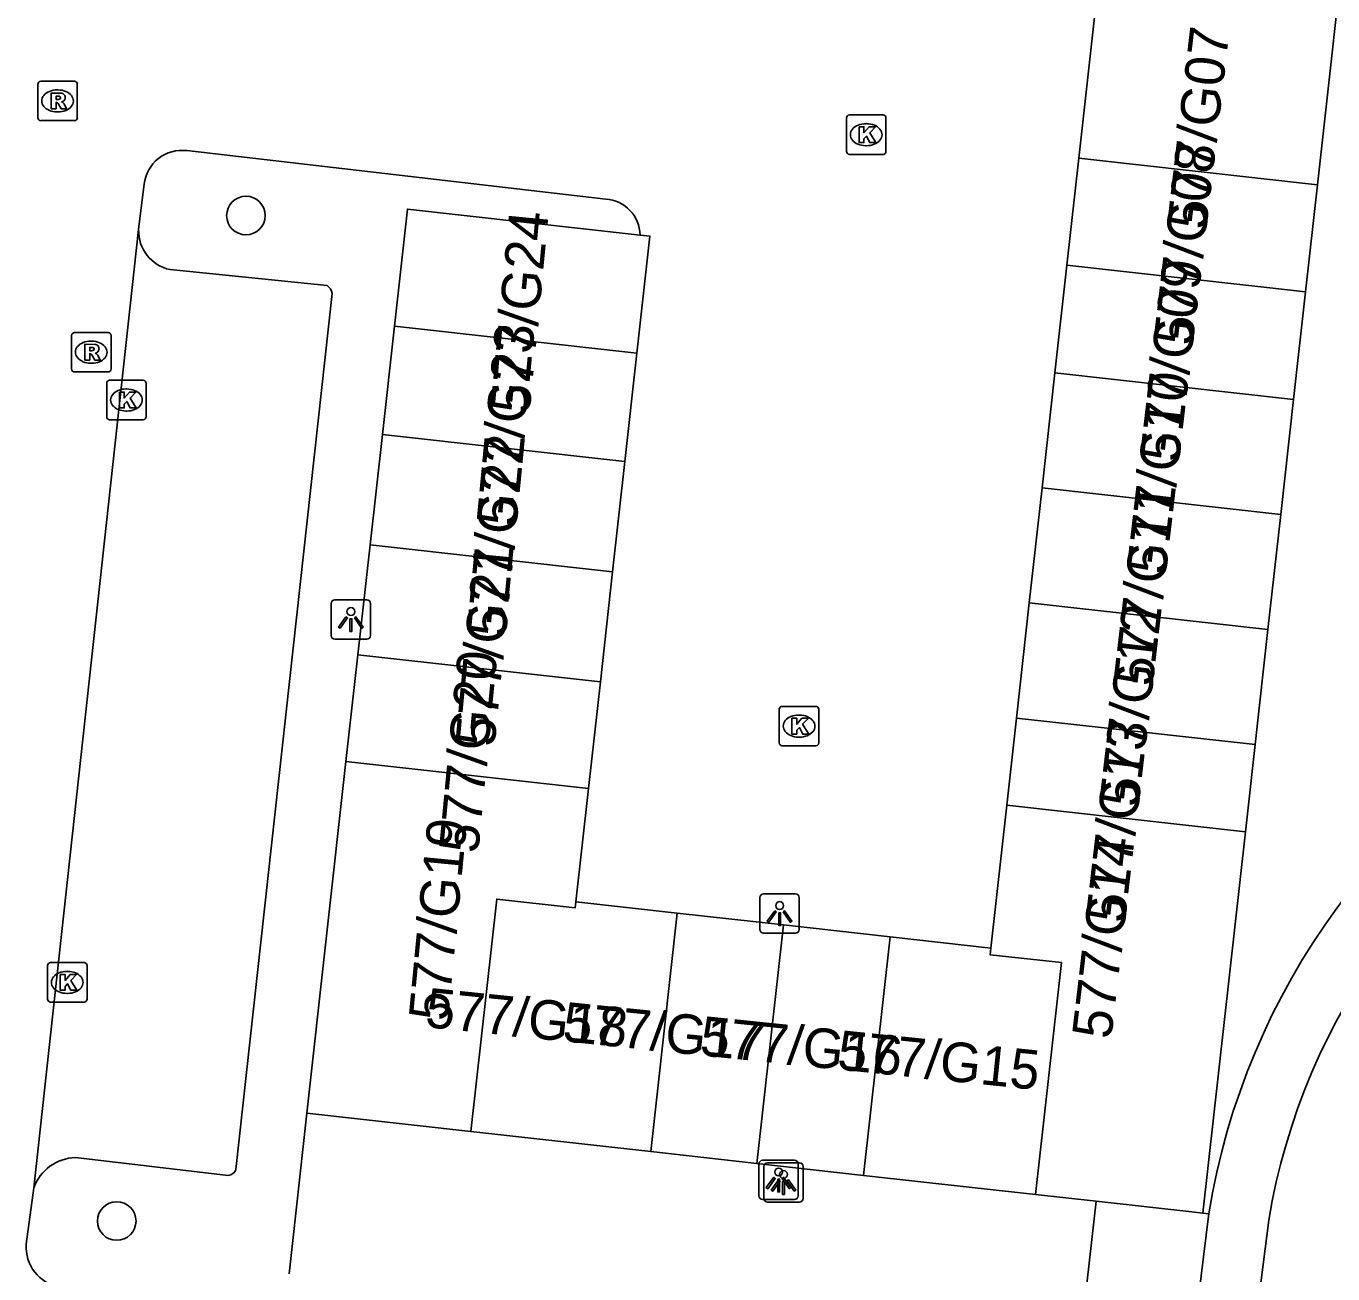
# Model space of a CAD drawing. Extents: x 162026 to 163499, y 387297 to 388169.
# Drawn here: x 162162.16 to 162195.29, y 387957.96 to 387989.59 of the extents above; entities that cross this region are included whole.
import ezdxf

# ---------------------------------------------------------------- set-up
doc = ezdxf.new("R2010")
doc.units = 0
for name, color, linetype in [('IMGEO_Boom', 7, 'Continuous'), ('IMGEO_Groenvoorziening', 7, 'Continuous'), ('IMGEO_Kolk', 7, 'Continuous'), ('IMGEO_Lichtpunt', 7, 'Continuous'), ('IMGEO_Pand', 7, 'Continuous'), ('IMGEO_Pand_nummerreeks', 7, 'Continuous'), ('IMGEO_Parkeervlak_open', 7, 'Continuous'), ('IMGEO_Rijbaan_lokaal_open', 7, 'Continuous'), ('IMGEO_Rioolput', 7, 'Continuous'), ('IMGEO_Voetpad_open', 7, 'Continuous')]:
    doc.layers.add(name, color=color, linetype=linetype)

msp = doc.modelspace()

# ---------------------------------------------------------------- linework, layer by layer
at = {"layer": 'IMGEO_Boom'}
for centre in [(162167.731, 387984.79), (162164.456, 387959.299)]:
    msp.add_circle(centre, 0.489, dxfattribs=at)
at = {"layer": 'IMGEO_Groenvoorziening'}
msp.add_lwpolyline([(162191.994, 387959.499), (162192.14, 387959.482)], dxfattribs=at)
at = {"layer": 'IMGEO_Kolk'}
for p, q in [((162182.955, 387986.414), (162182.955, 387987.266)), ((162183.03, 387987.34), (162183.882, 387987.34)), ((162183.443, 387987.12), (162183.468, 387987.12)), ((162183.956, 387987.266), (162183.956, 387986.414)), ((162183.466, 387986.56), (162183.441, 387986.56)), ((162183.882, 387986.34), (162183.03, 387986.34)), ((162164.201, 387979.688), (162164.201, 387980.54)), ((162164.276, 387980.614), (162165.128, 387980.614)), ((162165.202, 387980.54), (162165.202, 387979.688)), ((162164.689, 387980.394), (162164.714, 387980.394)), ((162164.712, 387979.834), (162164.687, 387979.834)), ((162165.128, 387979.614), (162164.276, 387979.614)), ((162181.253, 387971.42), (162181.253, 387972.272)), ((162181.328, 387972.346), (162182.18, 387972.346)), ((162182.254, 387972.272), (162182.254, 387971.42)), ((162181.741, 387972.126), (162181.766, 387972.126)), ((162181.764, 387971.566), (162181.739, 387971.566)), ((162182.18, 387971.346), (162181.328, 387971.346)), ((162162.701, 387964.923), (162162.701, 387965.775)), ((162162.776, 387965.849), (162163.628, 387965.849)), ((162163.189, 387965.629), (162163.214, 387965.629)), ((162163.702, 387965.775), (162163.702, 387964.923)), ((162163.212, 387965.069), (162163.187, 387965.069)), ((162163.628, 387964.849), (162162.776, 387964.849))]:
    msp.add_line(p, q, dxfattribs=at)
for points in [[(162182.955, 387986.414), (162182.955, 387987.266)], [(162183.03, 387987.34), (162183.882, 387987.34)], [(162183.956, 387987.266), (162183.956, 387986.414)], [(162183.276, 387987.04), (162183.399, 387987.04), (162183.399, 387986.889), (162183.529, 387987.04), (162183.693, 387987.04), (162183.547, 387986.889), (162183.7, 387986.64), (162183.548, 387986.64), (162183.463, 387986.804), (162183.399, 387986.737), (162183.399, 387986.64), (162183.276, 387986.64), (162183.276, 387987.04)], [(162183.882, 387986.34), (162183.03, 387986.34)], [(162164.201, 387979.688), (162164.201, 387980.54)], [(162164.276, 387980.614), (162165.128, 387980.614)], [(162165.202, 387980.54), (162165.202, 387979.688)], [(162164.522, 387980.314), (162164.645, 387980.314), (162164.645, 387980.163), (162164.775, 387980.314), (162164.939, 387980.314), (162164.793, 387980.163), (162164.946, 387979.914), (162164.794, 387979.914), (162164.709, 387980.078), (162164.645, 387980.011), (162164.645, 387979.914), (162164.522, 387979.914), (162164.522, 387980.314)], [(162165.128, 387979.614), (162164.276, 387979.614)], [(162181.253, 387971.42), (162181.253, 387972.272)], [(162181.328, 387972.346), (162182.18, 387972.346)], [(162182.254, 387972.272), (162182.254, 387971.42)], [(162181.574, 387972.046), (162181.697, 387972.046), (162181.697, 387971.895), (162181.827, 387972.046), (162181.991, 387972.046), (162181.845, 387971.895), (162181.998, 387971.646), (162181.846, 387971.646), (162181.761, 387971.81), (162181.697, 387971.743), (162181.697, 387971.646), (162181.574, 387971.646), (162181.574, 387972.046)], [(162182.18, 387971.346), (162181.328, 387971.346)], [(162162.701, 387964.923), (162162.701, 387965.775)], [(162162.776, 387965.849), (162163.628, 387965.849)], [(162163.702, 387965.775), (162163.702, 387964.923)], [(162163.022, 387965.549), (162163.145, 387965.549), (162163.145, 387965.398), (162163.275, 387965.549), (162163.439, 387965.549), (162163.293, 387965.398), (162163.446, 387965.149), (162163.294, 387965.149), (162163.209, 387965.313), (162163.145, 387965.246), (162163.145, 387965.149), (162163.022, 387965.149), (162163.022, 387965.549)], [(162163.628, 387964.849), (162162.776, 387964.849)]]:
    msp.add_lwpolyline(points, dxfattribs=at)
for centre, start, end in [((162183.032, 387987.264), 91.552, 178.448), ((162183.032, 387987.264), 91.552, 178.448), ((162183.88, 387987.264), 1.552, 88.448), ((162183.88, 387987.264), 1.552, 88.448), ((162183.032, 387986.416), 181.552, 268.448), ((162183.032, 387986.416), 181.552, 268.448), ((162183.88, 387986.416), 271.552, 358.448), ((162183.88, 387986.416), 271.552, 358.448), ((162164.278, 387980.538), 91.552, 178.448), ((162164.278, 387980.538), 91.552, 178.448), ((162165.126, 387980.538), 1.552, 88.448), ((162165.126, 387980.538), 1.552, 88.448), ((162164.278, 387979.69), 181.552, 268.448), ((162164.278, 387979.69), 181.552, 268.448), ((162165.126, 387979.69), 271.552, 358.448), ((162165.126, 387979.69), 271.552, 358.448), ((162181.33, 387972.27), 91.552, 178.448), ((162181.33, 387972.27), 91.552, 178.448), ((162182.178, 387972.27), 1.552, 88.448), ((162182.178, 387972.27), 1.552, 88.448), ((162181.33, 387971.422), 181.552, 268.448), ((162181.33, 387971.422), 181.552, 268.448), ((162182.178, 387971.422), 271.552, 358.448), ((162182.178, 387971.422), 271.552, 358.448), ((162162.778, 387965.773), 91.552, 178.448), ((162162.778, 387965.773), 91.552, 178.448), ((162163.626, 387965.773), 1.552, 88.448), ((162163.626, 387965.773), 1.552, 88.448), ((162162.778, 387964.925), 181.552, 268.448), ((162162.778, 387964.925), 181.552, 268.448), ((162163.626, 387964.925), 271.552, 358.448), ((162163.626, 387964.925), 271.552, 358.448)]:
    msp.add_arc(centre, 0.0765, start, end, dxfattribs=at)
for centre, major_axis, ratio, start_param, end_param in [((162183.442, 387986.84), (-0.387, 0.002), 0.722429, 4.712389, 7.853982), ((162183.467, 387986.84), (-0.39, 0.002), 0.717154, 1.570796, 4.712389), ((162164.688, 387980.114), (-0.387, 0.002), 0.722429, 4.712389, 7.853982), ((162164.713, 387980.114), (-0.39, 0.002), 0.717154, 1.570796, 4.712389), ((162181.74, 387971.846), (-0.387, 0.002), 0.722429, 4.712389, 7.853982), ((162181.765, 387971.846), (-0.39, 0.002), 0.717154, 1.570796, 4.712389), ((162163.188, 387965.349), (-0.387, 0.002), 0.722429, 4.712389, 7.853982), ((162163.213, 387965.349), (-0.39, 0.002), 0.717154, 1.570796, 4.712389)]:
    msp.add_ellipse(centre, major_axis=major_axis, ratio=ratio, start_param=start_param, end_param=end_param, dxfattribs=at)
at = {"layer": 'IMGEO_Lichtpunt'}
for p, q in [((162169.893, 387974.952), (162169.893, 387974.145)), ((162169.893, 387974.952), (162169.893, 387974.145)), ((162170.795, 387975.047), (162169.987, 387975.047)), ((162170.795, 387975.047), (162169.987, 387975.047)), ((162170.889, 387974.145), (162170.889, 387974.952)), ((162170.889, 387974.145), (162170.889, 387974.952)), ((162169.987, 387974.051), (162170.795, 387974.051)), ((162169.987, 387974.051), (162170.795, 387974.051)), ((162181.664, 387967.593), (162180.856, 387967.593)), ((162181.664, 387967.593), (162180.856, 387967.593)), ((162180.762, 387967.498), (162180.762, 387966.691)), ((162180.762, 387967.498), (162180.762, 387966.691)), ((162181.758, 387966.691), (162181.758, 387967.498)), ((162181.758, 387966.691), (162181.758, 387967.498)), ((162180.856, 387966.597), (162181.664, 387966.597)), ((162180.856, 387966.597), (162181.664, 387966.597)), ((162180.737, 387960.744), (162180.737, 387959.937)), ((162180.737, 387960.744), (162180.737, 387959.937)), ((162181.639, 387960.839), (162180.831, 387960.839)), ((162181.639, 387960.839), (162180.831, 387960.839)), ((162180.86, 387960.681), (162180.86, 387959.874)), ((162180.86, 387960.681), (162180.86, 387959.874)), ((162181.762, 387960.776), (162180.954, 387960.776)), ((162181.762, 387960.776), (162180.954, 387960.776)), ((162181.733, 387959.937), (162181.733, 387960.744)), ((162181.733, 387959.937), (162181.733, 387960.744)), ((162181.856, 387959.874), (162181.856, 387960.681)), ((162181.856, 387959.874), (162181.856, 387960.681)), ((162180.831, 387959.843), (162181.639, 387959.843)), ((162180.831, 387959.843), (162181.639, 387959.843)), ((162180.954, 387959.78), (162181.762, 387959.78)), ((162180.954, 387959.78), (162181.762, 387959.78))]:
    msp.add_line(p, q, dxfattribs=at)
for points in [[(162170.267, 387974.616), (162170.306, 387974.588), (162170.118, 387974.326), (162170.08, 387974.353), (162170.267, 387974.616)], [(162170.369, 387974.568), (162170.416, 387974.568), (162170.416, 387974.246), (162170.369, 387974.246), (162170.369, 387974.568)], [(162170.479, 387974.588), (162170.517, 387974.615), (162170.704, 387974.353), (162170.665, 387974.325), (162170.479, 387974.588)], [(162181.136, 387967.162), (162181.175, 387967.134), (162180.987, 387966.872), (162180.949, 387966.899), (162181.136, 387967.162)], [(162181.238, 387967.114), (162181.285, 387967.114), (162181.285, 387966.792), (162181.238, 387966.792), (162181.238, 387967.114)], [(162181.348, 387967.134), (162181.386, 387967.161), (162181.573, 387966.899), (162181.534, 387966.871), (162181.348, 387967.134)], [(162181.111, 387960.408), (162181.15, 387960.38), (162180.962, 387960.118), (162180.924, 387960.145), (162181.111, 387960.408)], [(162181.234, 387960.345), (162181.273, 387960.317), (162181.085, 387960.055), (162181.047, 387960.082), (162181.234, 387960.345)], [(162181.213, 387960.36), (162181.26, 387960.36), (162181.26, 387960.038), (162181.213, 387960.038), (162181.213, 387960.36)], [(162181.323, 387960.38), (162181.361, 387960.407), (162181.548, 387960.145), (162181.509, 387960.117), (162181.323, 387960.38)], [(162181.336, 387960.297), (162181.383, 387960.297), (162181.383, 387959.975), (162181.336, 387959.975), (162181.336, 387960.297)], [(162181.446, 387960.317), (162181.484, 387960.344), (162181.671, 387960.082), (162181.632, 387960.054), (162181.446, 387960.317)]]:
    msp.add_lwpolyline(points, dxfattribs=at)
for centre in [(162170.392, 387974.75), (162181.261, 387967.296), (162181.236, 387960.542), (162181.359, 387960.479)]:
    msp.add_circle(centre, 0.0994, dxfattribs=at)
for centre, start, end in [((162169.987, 387974.952), 90, 180), ((162169.987, 387974.952), 90, 180), ((162170.795, 387974.952), 0, 90), ((162170.795, 387974.952), 0, 90), ((162169.987, 387974.145), 180, 270), ((162169.987, 387974.145), 180, 270), ((162170.795, 387974.145), 270, 0), ((162170.795, 387974.145), 270, 360), ((162180.856, 387967.498), 90, 180), ((162180.856, 387967.498), 90, 180), ((162181.664, 387967.498), 0, 90), ((162181.664, 387967.498), 0, 90), ((162180.856, 387966.691), 180, 270), ((162180.856, 387966.691), 180, 270), ((162181.664, 387966.691), 270, 0), ((162181.664, 387966.691), 270, 360), ((162180.831, 387960.744), 90, 180), ((162180.831, 387960.744), 90, 180), ((162180.954, 387960.681), 90, 180), ((162180.954, 387960.681), 90, 180), ((162181.639, 387960.744), 0, 90), ((162181.639, 387960.744), 0, 90), ((162181.762, 387960.681), 0, 90), ((162181.762, 387960.681), 0, 90), ((162180.831, 387959.937), 180, 270), ((162180.831, 387959.937), 180, 270), ((162180.954, 387959.874), 180, 270), ((162180.954, 387959.874), 180, 270), ((162181.639, 387959.937), 270, 0), ((162181.639, 387959.937), 270, 360), ((162181.762, 387959.874), 270, 0), ((162181.762, 387959.874), 270, 360)]:
    msp.add_arc(centre, 0.0946, start, end, dxfattribs=at)
at = {"layer": 'IMGEO_Pand'}
for points in [[(162195.997, 387995.446), (162195.72, 387992.96), (162194.897, 387985.573)], [(162188.847, 387986.247), (162189.254, 387989.898)], [(162188.545, 387983.533), (162188.847, 387986.247)], [(162194.897, 387985.573), (162188.847, 387986.247)], [(162194.897, 387985.573), (162194.595, 387982.858)], [(162171.496, 387981.989), (162171.826, 387984.953), (162177.724, 387984.296)], [(162177.724, 387984.296), (162177.974, 387984.268), (162177.644, 387981.304)], [(162188.241, 387980.8), (162188.545, 387983.533)], [(162188.545, 387983.533), (162194.595, 387982.858)], [(162194.595, 387982.858), (162194.291, 387980.125)], [(162171.496, 387981.989), (162171.189, 387979.236)], [(162177.644, 387981.304), (162171.496, 387981.989)], [(162177.644, 387981.304), (162177.338, 387978.551)], [(162187.916, 387977.884), (162188.241, 387980.8)], [(162194.291, 387980.125), (162188.241, 387980.8)], [(162194.291, 387980.125), (162193.966, 387977.21)], [(162170.878, 387976.446), (162171.189, 387979.236)], [(162171.189, 387979.236), (162177.338, 387978.551)], [(162177.338, 387978.551), (162177.027, 387975.761)], [(162187.591, 387974.968), (162187.916, 387977.884)], [(162193.966, 387977.21), (162187.916, 387977.884)], [(162193.966, 387977.21), (162193.642, 387974.294)], [(162170.878, 387976.446), (162170.568, 387973.656)], [(162177.027, 387975.761), (162170.878, 387976.446)], [(162177.027, 387975.761), (162176.716, 387972.971)], [(162187.267, 387972.051), (162187.591, 387974.968)], [(162187.591, 387974.968), (162193.642, 387974.294)], [(162193.642, 387974.294), (162193.317, 387971.378)], [(162170.568, 387973.656), (162170.266, 387970.951)], [(162170.568, 387973.656), (162176.716, 387972.971)], [(162176.716, 387972.971), (162176.415, 387970.266)], [(162187.021, 387969.842), (162187.267, 387972.051)], [(162193.317, 387971.378), (162187.267, 387972.051)], [(162193.317, 387971.378), (162193.07, 387969.166)], [(162170.266, 387970.951), (162169.273, 387962.029)], [(162176.415, 387970.266), (162170.266, 387970.951)], [(162176.415, 387970.266), (162176.095, 387967.391)], [(162186.617, 387966.219), (162187.021, 387969.842)], [(162187.021, 387969.842), (162193.07, 387969.166)], [(162193.07, 387969.166), (162192.667, 387965.544), (162191.994, 387959.499)], [(162173.436, 387961.565), (162174.091, 387967.462), (162176.078, 387967.241), (162176.095, 387967.391)], [(162176.095, 387967.391), (162178.666, 387967.105)], [(162178.666, 387967.105), (162177.993, 387961.058)], [(162178.666, 387967.105), (162181.356, 387966.805)], [(162180.683, 387960.759), (162181.356, 387966.805)], [(162181.356, 387966.805), (162184.063, 387966.503)], [(162184.063, 387966.503), (162183.39, 387960.457)], [(162184.063, 387966.503), (162186.617, 387966.219)], [(162187.75, 387959.972), (162188.404, 387965.849), (162186.598, 387966.05), (162186.617, 387966.219)], [(162169.273, 387962.029), (162173.436, 387961.565)], [(162177.993, 387961.058), (162173.436, 387961.565)], [(162177.993, 387961.058), (162180.683, 387960.759)], [(162180.683, 387960.759), (162183.39, 387960.457)], [(162183.39, 387960.457), (162187.75, 387959.972)], [(162189.287, 387959.801), (162187.75, 387959.972)], [(162191.994, 387959.499), (162191.711, 387959.531), (162189.287, 387959.801)]]:
    msp.add_lwpolyline(points, dxfattribs=at)
at = {"layer": 'IMGEO_Parkeervlak_open'}
for points in [[(162169.788, 387983.02), (162165.809, 387983.419)], [(162167.475, 387960.608), (162169.921, 387982.811)], [(162168.825, 387957.959), (162169.273, 387962.029)], [(162163.406, 387960.91), (162167.28, 387960.456)], [(162188.821, 387955.689), (162189.287, 387959.801)]]:
    msp.add_lwpolyline(points, dxfattribs=at)
for centre, radius, start, end in [((162166.013, 387984.401), 1.003, 178.1488, 258.2554), ((162169.581, 387982.742), 0.347, 11.5485, 53.3939), ((162163.454, 387959.736), 1.175, 92.3531, 159.8243), ((162167.273, 387960.667), 0.211, 272.0368, 343.8352)]:
    msp.add_arc(centre, radius, start, end, dxfattribs=at)
at = {"layer": 'IMGEO_Rijbaan_lokaal_open'}
for points in [[(162166.233, 387986.436), (162176.852, 387985.209)], [(162165.011, 387984.433), (162165.028, 387984.584), (162165.15, 387985.584)], [(162162.351, 387960.141), (162165.011, 387984.433)], [(162162.161, 387958.71), (162162.351, 387960.141)]]:
    msp.add_lwpolyline(points, dxfattribs=at)
for centre, radius, start, end in [((162166.11, 387985.478), 0.966, 82.6947, 173.6898), ((162176.787, 387984.274), 0.938, 1.3664, 86.002), ((162163.182, 387958.636), 1.023, 175.8798, 260.2286)]:
    msp.add_arc(centre, radius, start, end, dxfattribs=at)
at = {"layer": 'IMGEO_Rioolput'}
for p, q in [((162162.455, 387987.27), (162162.455, 387988.122)), ((162162.53, 387988.196), (162163.382, 387988.196)), ((162163.456, 387988.122), (162163.456, 387987.27)), ((162162.943, 387987.976), (162162.968, 387987.976)), ((162163.382, 387987.196), (162162.53, 387987.196)), ((162162.966, 387987.416), (162162.941, 387987.416)), ((162163.384, 387981.826), (162164.236, 387981.826)), ((162163.309, 387980.9), (162163.309, 387981.752)), ((162163.797, 387981.606), (162163.822, 387981.606)), ((162164.31, 387981.752), (162164.31, 387980.9)), ((162164.236, 387980.826), (162163.384, 387980.826)), ((162163.82, 387981.046), (162163.795, 387981.046))]:
    msp.add_line(p, q, dxfattribs=at)
for points in [[(162162.455, 387987.27), (162162.455, 387988.122)], [(162162.53, 387988.196), (162163.382, 387988.196)], [(162163.456, 387988.122), (162163.456, 387987.27)], [(162163.044, 387987.894), (162162.792, 387987.896), (162162.792, 387987.496)], [(162162.97, 387987.815), (162162.916, 387987.815), (162162.916, 387987.734)], [(162162.792, 387987.496), (162162.916, 387987.496), (162162.916, 387987.658), (162162.927, 387987.658)], [(162162.916, 387987.734), (162162.968, 387987.734)], [(162162.974, 387987.629), (162163.045, 387987.496), (162163.185, 387987.496), (162163.12, 387987.622)], [(162163.382, 387987.196), (162162.53, 387987.196)], [(162163.384, 387981.826), (162164.236, 387981.826)], [(162163.309, 387980.9), (162163.309, 387981.752)], [(162163.898, 387981.524), (162163.646, 387981.526), (162163.646, 387981.126)], [(162164.31, 387981.752), (162164.31, 387980.9)], [(162163.646, 387981.126), (162163.77, 387981.126), (162163.77, 387981.288), (162163.781, 387981.288)], [(162163.824, 387981.445), (162163.77, 387981.445), (162163.77, 387981.364)], [(162163.77, 387981.364), (162163.822, 387981.364)], [(162163.828, 387981.259), (162163.899, 387981.126), (162164.039, 387981.126), (162163.974, 387981.252)], [(162164.236, 387980.826), (162163.384, 387980.826)]]:
    msp.add_lwpolyline(points, dxfattribs=at)
for centre, radius, start, end in [((162162.532, 387988.12), 0.0765, 91.552, 178.448), ((162162.532, 387988.12), 0.0765, 91.552, 178.448), ((162163.38, 387988.12), 0.0765, 1.552, 88.448), ((162163.38, 387988.12), 0.0765, 1.552, 88.448), ((162162.976, 387987.719), 0.0964, 77.0061, 93.1865), ((162162.99, 387987.776), 0.0378, 276.6634, 79.6772), ((162163.043, 387987.784), 0.109, 350.3612, 89.416), ((162162.926, 387987.605), 0.0533, 26.0293, 88.6989), ((162162.952, 387987.923), 0.19, 274.7715, 282.9687), ((162163.041, 387987.784), 0.112, 277.5842, 350.9817), ((162163.025, 387987.569), 0.108, 29.5134, 73.7905), ((162162.532, 387987.272), 0.0765, 181.552, 268.448), ((162162.532, 387987.272), 0.0765, 181.552, 268.448), ((162163.38, 387987.272), 0.0765, 271.552, 358.448), ((162163.38, 387987.272), 0.0765, 271.552, 358.448), ((162163.386, 387981.75), 0.0765, 91.552, 178.448), ((162163.386, 387981.75), 0.0765, 91.552, 178.448), ((162164.234, 387981.75), 0.0765, 1.552, 88.448), ((162164.234, 387981.75), 0.0765, 1.552, 88.448), ((162163.897, 387981.414), 0.109, 350.3612, 89.416), ((162163.78, 387981.235), 0.0533, 26.0293, 88.6989), ((162163.806, 387981.553), 0.19, 274.7715, 282.9687), ((162163.83, 387981.349), 0.0964, 77.0061, 93.1865), ((162163.844, 387981.406), 0.0378, 276.6634, 79.6772), ((162163.895, 387981.414), 0.112, 277.5842, 350.9817), ((162163.879, 387981.199), 0.108, 29.5134, 73.7905), ((162163.386, 387980.902), 0.0765, 181.552, 268.448), ((162163.386, 387980.902), 0.0765, 181.552, 268.448), ((162164.234, 387980.902), 0.0765, 271.552, 358.448), ((162164.234, 387980.902), 0.0765, 271.552, 358.448)]:
    msp.add_arc(centre, radius, start, end, dxfattribs=at)
for centre, major_axis, ratio, start_param, end_param in [((162162.942, 387987.696), (-0.387, 0.002), 0.722429, 4.712389, 7.853982), ((162162.967, 387987.696), (-0.39, 0.002), 0.717154, 1.570796, 4.712389), ((162163.796, 387981.326), (-0.387, 0.002), 0.722429, 4.712389, 7.853982), ((162163.821, 387981.326), (-0.39, 0.002), 0.717154, 1.570796, 4.712389)]:
    msp.add_ellipse(centre, major_axis=major_axis, ratio=ratio, start_param=start_param, end_param=end_param, dxfattribs=at)
at = {"layer": 'IMGEO_Voetpad_open'}
for points in [[(162192.14, 387959.482), (162192.131, 387959.426), (162191.516, 387954.405)], [(162195.019, 387954.965), (162193.133, 387955.152), (162193.664, 387959.321)]]:
    msp.add_lwpolyline(points, dxfattribs=at)
for centre, radius, start, end in [((162209.874, 387956.607), 17.965, 116.7271, 170.792), ((162209.805, 387956.652), 16.361, 116.181, 170.6106)]:
    msp.add_arc(centre, radius, start, end, dxfattribs=at)

# ---------------------------------------------------------------- texts
at = {"layer": 'IMGEO_Pand_nummerreeks'}
for s, rotation, p in [('577/G07', 83.3046, (162192.073, 387984.413)), ('577/G08', 83.3046, (162191.728, 387981.471)), ('577/G24', 84.5285, (162174.918, 387979.748)), ('577/G09', 83.3046, (162191.382, 387978.52)), ('577/G23', 84.5273, (162174.569, 387976.897)), ('577/G10', 83.3046, (162191.047, 387975.672)), ('577/G22', 84.5273, (162174.318, 387974.084)), ('577/G11', 83.3046, (162190.714, 387972.833)), ('577/G21', 84.5273, (162174.033, 387971.304)), ('577/G12', 83.3046, (162190.355, 387969.772)), ('577/G20', 84.5273, (162173.618, 387968.602)), ('577/G13', 83.3046, (162190.01, 387966.833)), ('577/G19', 84.5273, (162172.85, 387964.349)), ('577/G14', 83.3023, (162189.664, 387963.888)), ('577/G18', 354.1226, (162172.252, 387964.219)), ('577/G17', 354.1226, (162175.732, 387963.861)), ('577/G16', 354.1226, (162179.214, 387963.503)), ('577/G15', 354.1226, (162182.697, 387963.144))]:
    msp.add_text(s, height=1, rotation=rotation, dxfattribs=at).set_placement(p)

doc.saveas('drawing.dxf')
